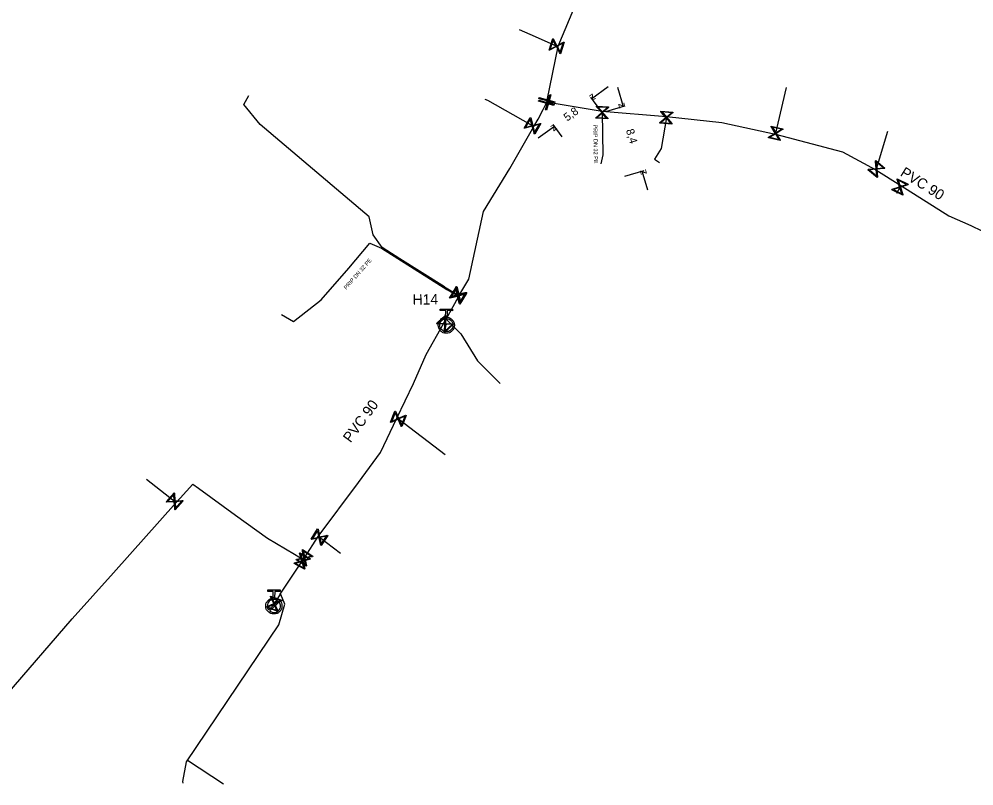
# Model space of a CAD drawing. Extents: x -641905 to -641246, y -1111750 to -1110210.
# Drawn here: x -641545.3 to -641426.1, y -1110592 to -1110496.2 of the extents above; entities that cross this region are included whole.
import ezdxf

# ---------------------------------------------------------------- set-up
doc = ezdxf.new("R2010")
doc.units = 0
for name, color, linetype in [('Default', 7, 'Continuous'), ('VP Hydrant', 7, 'Continuous'), ('VP Hydrant - popis', 7, 'Continuous'), ('VP Kótování', 7, 'Continuous'), ('VP Popis přípojky', 7, 'Continuous'), ('VP Přípojka', 7, 'Continuous'), ('VP Řad', 7, 'Continuous'), ('VP Řad - popis', 7, 'Continuous'), ('VP Šoupě', 7, 'Continuous')]:
    doc.layers.add(name, color=color, linetype=linetype)

msp = doc.modelspace()

# ---------------------------------------------------------------- linework, layer by layer
at = {"layer": 'Default'}
for points in [[(-641491.88, -1110533.45), (-641491.52, -1110533.49), (-641491.27, -1110533.75), (-641490.98, -1110534.04), (-641490.98, -1110534.46), (-641490.98, -1110534.87), (-641491.28, -1110535.16), (-641491.57, -1110535.45), (-641491.99, -1110535.45), (-641492.4, -1110535.45), (-641492.69, -1110535.15), (-641492.98, -1110534.86), (-641492.98, -1110534.45), (-641492.98, -1110534.03), (-641492.69, -1110533.74), (-641492.43, -1110533.48), (-641492.07, -1110533.45)], [(-641491.98, -1110533.64), (-641492.32, -1110533.63), (-641492.55, -1110533.87), (-641492.79, -1110534.11), (-641492.79, -1110534.44), (-641492.8, -1110534.78), (-641492.56, -1110535.02), (-641492.32, -1110535.26), (-641491.99, -1110535.26), (-641491.65, -1110535.26), (-641491.41, -1110535.03), (-641491.17, -1110534.79), (-641491.17, -1110534.45), (-641491.17, -1110534.11), (-641491.4, -1110533.88), (-641491.64, -1110533.64), (-641491.98, -1110533.64)], [(-641513.42, -1110568.51), (-641513.06, -1110568.54), (-641512.8, -1110568.8), (-641512.51, -1110569.1), (-641512.51, -1110569.51), (-641512.52, -1110569.93), (-641512.81, -1110570.22), (-641513.1, -1110570.51), (-641513.52, -1110570.51), (-641513.93, -1110570.5), (-641514.22, -1110570.21), (-641514.52, -1110569.92), (-641514.51, -1110569.5), (-641514.51, -1110569.09), (-641514.22, -1110568.8), (-641513.96, -1110568.54), (-641513.6, -1110568.51)], [(-641513, -1110568.87), (-641513.22, -1110568.69), (-641513.51, -1110568.69), (-641513.85, -1110568.69), (-641514.09, -1110568.93), (-641514.33, -1110569.16), (-641514.33, -1110569.5), (-641514.33, -1110569.79), (-641514.15, -1110570.01)], [(-641514.02, -1110570.14), (-641513.81, -1110570.32), (-641513.52, -1110570.32), (-641513.18, -1110570.32), (-641512.94, -1110570.08), (-641512.7, -1110569.85), (-641512.7, -1110569.51), (-641512.7, -1110569.22), (-641512.87, -1110569)]]:
    msp.add_open_spline(points, degree=3, dxfattribs=at)
at = {"layer": 'VP Hydrant'}
for points in [[(-641492.07, -1110533.45), (-641492.06, -1110532.63), (-641492.75, -1110532.63), (-641492.75, -1110532.45), (-641491.19, -1110532.45), (-641491.19, -1110532.64), (-641491.88, -1110532.63), (-641491.88, -1110533.45)], [(-641513.6, -1110568.51), (-641513.6, -1110567.69), (-641514.28, -1110567.69), (-641514.28, -1110567.5), (-641512.72, -1110567.51), (-641512.72, -1110567.69), (-641513.41, -1110567.69), (-641513.42, -1110568.51)], [(-641514.15, -1110570.01), (-641513, -1110568.87)], [(-641512.87, -1110569), (-641514.02, -1110570.14)]]:
    msp.add_lwpolyline(points, dxfattribs=at)
at = {"layer": 'VP Kótování'}
for points in [[(-641471.79, -1110504.7), (-641473.81, -1110506.18)], [(-641470.61, -1110504.75), (-641469.91, -1110507.15)], [(-641472.83, -1110507.52), (-641473.95, -1110505.97)], [(-641472.05, -1110507.78), (-641469.67, -1110507.08)], [(-641480.51, -1110511.07), (-641478.49, -1110509.59)], [(-641477.51, -1110510.94), (-641478.64, -1110509.39)], [(-641469.68, -1110515.84), (-641467.29, -1110515.14)], [(-641466.83, -1110517.6), (-641467.53, -1110515.21)]]:
    msp.add_lwpolyline(points, dxfattribs=at)
at = {"layer": 'VP Přípojka'}
for points in [[(-641478.05, -1110499.66), (-641478.21, -1110499.61), (-641481.53, -1110498.14), (-641482.83, -1110497.56)], [(-641450.89, -1110510.61), (-641450.84, -1110510.49), (-641449.48, -1110504.79)], [(-641497.77, -1110526.15), (-641500, -1110524.75), (-641501.13, -1110523.18), (-641501.62, -1110520.94), (-641515.25, -1110509.4), (-641517.29, -1110506.9), (-641516.63, -1110505.77)], [(-641481.05, -1110509.66), (-641481.22, -1110509.56), (-641481.42, -1110509.44), (-641486.8, -1110506.39), (-641487.11, -1110506.26)], [(-641472.51, -1110507.72), (-641472.52, -1110507.9), (-641472.42, -1110513.2), (-641472.68, -1110514.32)], [(-641464.49, -1110508.41), (-641464.5, -1110508.53), (-641465.16, -1110512.38), (-641465.98, -1110513.73), (-641465.34, -1110514.13)], [(-641438.36, -1110515.06), (-641438.26, -1110514.94), (-641436.83, -1110510.21)], [(-641435.7, -1110517.96), (-641435.32, -1110517.2)], [(-641435.32, -1110517.2), (-641435.23, -1110517.02)], [(-641512.58, -1110533.12), (-641511.08, -1110534), (-641507.6, -1110531.28), (-641504.14, -1110527.32), (-641501.53, -1110524.21), (-641500.07, -1110524.85), (-641491.9, -1110529.99), (-641490.54, -1110530.8)], [(-641492.19, -1110529.66), (-641497.77, -1110526.15)], [(-641492.19, -1110529.66), (-641490.47, -1110530.7), (-641490.4, -1110530.78)], [(-641490.54, -1110530.8), (-641490.46, -1110530.91)], [(-641491.98, -1110534.45), (-641492.13, -1110534.28), (-641492.29, -1110534.19)], [(-641492.02, -1110533.7), (-641491.95, -1110533.73), (-641490.17, -1110535.55), (-641488.09, -1110538.91), (-641485.24, -1110541.74)], [(-641498.15, -1110546.07), (-641497.97, -1110546.14), (-641492.14, -1110550.62)], [(-641525.73, -1110556.61), (-641525.91, -1110556.45), (-641529.44, -1110553.71)], [(-641507.97, -1110560.85), (-641507.83, -1110560.94), (-641505.19, -1110562.91)], [(-641512.74, -1110568.02), (-641513.48, -1110569.24), (-641513.52, -1110569.5)], [(-641519.79, -1110591.77), (-641524.31, -1110588.81)]]:
    msp.add_lwpolyline(points, dxfattribs=at)
at = {"layer": 'VP Řad'}
for points in [[(-641472.59, -1110486.61), (-641478.05, -1110499.66), (-641479.43, -1110506.37), (-641479.47, -1110506.59)], [(-641509.87, -1110563.7), (-641509.71, -1110563.52), (-641507.97, -1110560.85), (-641502.96, -1110554.08), (-641500.21, -1110550.36), (-641498.15, -1110546.07), (-641496.08, -1110541.72), (-641494.49, -1110538.1), (-641492.29, -1110534.19), (-641492.02, -1110533.7), (-641490.46, -1110530.91), (-641490.4, -1110530.78), (-641489.19, -1110528.69), (-641487.32, -1110520.26), (-641484.05, -1110514.87), (-641481.05, -1110509.66), (-641480.51, -1110508.72), (-641479.89, -1110507.54), (-641479.49, -1110506.7), (-641479.47, -1110506.59)], [(-641479.47, -1110506.59), (-641479.27, -1110506.62), (-641472.51, -1110507.72), (-641464.49, -1110508.41), (-641457.56, -1110509.13), (-641450.89, -1110510.61), (-641442.5, -1110512.82), (-641438.36, -1110515.06), (-641435.23, -1110517.02), (-641429.22, -1110520.79), (-641426.48, -1110522), (-641418.24, -1110525.99), (-641418.01, -1110526.1), (-641417.95, -1110526.12)], [(-641606.72, -1110649.72), (-641606.63, -1110649.64), (-641606.61, -1110649.53), (-641606.49, -1110649.41), (-641597.96, -1110641.06), (-641597.05, -1110639.76), (-641582.85, -1110623.35), (-641570.58, -1110609.06), (-641560.21, -1110596.51), (-641554.97, -1110589.92), (-641538.7, -1110571.11), (-641533.56, -1110565.36), (-641525.73, -1110556.61), (-641525.22, -1110556.04), (-641523.66, -1110554.29), (-641522.92, -1110554.82), (-641518.3, -1110558.16), (-641514.31, -1110561.04), (-641510.94, -1110563.03), (-641509.87, -1110563.7)], [(-641512.74, -1110568.02), (-641509.98, -1110563.9), (-641509.98, -1110563.9), (-641509.87, -1110563.7)], [(-641524.84, -1110591.63), (-641524.89, -1110591.45), (-641524.43, -1110588.98), (-641512.91, -1110571.86), (-641512.13, -1110569.29), (-641512.66, -1110568.07), (-641512.74, -1110568.02)]]:
    msp.add_lwpolyline(points, dxfattribs=at)
at = {"layer": 'VP Šoupě'}
for points in [[(-641477.27, -1110499.12), (-641477.72, -1110500.55), (-641477.78, -1110500.53), (-641477.84, -1110500.41), (-641478.23, -1110499.67), (-641479.09, -1110500.12), (-641479.15, -1110500.1), (-641478.7, -1110498.67), (-641478.64, -1110498.69), (-641478.19, -1110499.55), (-641477.45, -1110499.16), (-641477.33, -1110499.1), (-641477.27, -1110499.12)], [(-641479.01, -1110499.98), (-641478.27, -1110499.59), (-641478.66, -1110498.85), (-641479.01, -1110499.98)], [(-641477.41, -1110499.24), (-641478.15, -1110499.63), (-641477.76, -1110500.37), (-641477.41, -1110499.24)], [(-641478.49, -1110506.7), (-641480.41, -1110506.17), (-641480.38, -1110506.04), (-641478.45, -1110506.58), (-641478.49, -1110506.7)], [(-641479.6, -1110507.57), (-641479.06, -1110505.64), (-641478.94, -1110505.68), (-641479.48, -1110507.6), (-641479.6, -1110507.57)], [(-641478.54, -1110507.03), (-641480.47, -1110506.49), (-641480.44, -1110506.37), (-641478.51, -1110506.91), (-641478.54, -1110507.03)], [(-641473.23, -1110507.11), (-641471.73, -1110507.19), (-641471.73, -1110507.26), (-641471.83, -1110507.34), (-641472.46, -1110507.9), (-641471.81, -1110508.62), (-641471.81, -1110508.69), (-641473.31, -1110508.61), (-641473.31, -1110508.54), (-641472.58, -1110507.9), (-641473.14, -1110507.27), (-641473.23, -1110507.18), (-641473.23, -1110507.11)], [(-641473.08, -1110507.21), (-641472.52, -1110507.84), (-641471.89, -1110507.28), (-641473.08, -1110507.21)], [(-641480.19, -1110509.28), (-641480.94, -1110510.58), (-641481, -1110510.55), (-641481.03, -1110510.42), (-641481.25, -1110509.61), (-641482.19, -1110509.86), (-641482.24, -1110509.83), (-641481.49, -1110508.53), (-641481.43, -1110508.56), (-641481.19, -1110509.5), (-641480.37, -1110509.29), (-641480.25, -1110509.25), (-641480.19, -1110509.28)], [(-641471.96, -1110508.59), (-641472.52, -1110507.96), (-641473.15, -1110508.52), (-641471.96, -1110508.59)], [(-641465.18, -1110507.72), (-641463.69, -1110507.85), (-641463.69, -1110507.92), (-641463.79, -1110507.99), (-641464.44, -1110508.53), (-641463.81, -1110509.28), (-641463.82, -1110509.34), (-641465.31, -1110509.21), (-641465.31, -1110509.14), (-641464.56, -1110508.52), (-641465.1, -1110507.88), (-641465.19, -1110507.78), (-641465.18, -1110507.72)], [(-641463.96, -1110509.24), (-641464.51, -1110508.59), (-641465.15, -1110509.13), (-641463.96, -1110509.24)], [(-641465.03, -1110507.82), (-641464.49, -1110508.47), (-641463.85, -1110507.93), (-641465.03, -1110507.82)], [(-641482.08, -1110509.75), (-641481.27, -1110509.53), (-641481.49, -1110508.71), (-641482.08, -1110509.75)], [(-641480.35, -1110509.37), (-641481.16, -1110509.59), (-641480.95, -1110510.4), (-641480.35, -1110509.37)], [(-641451.4, -1110509.59), (-641449.94, -1110509.93), (-641449.95, -1110510), (-641450.06, -1110510.06), (-641450.78, -1110510.5), (-641450.27, -1110511.33), (-641450.28, -1110511.39), (-641451.74, -1110511.05), (-641451.73, -1110510.98), (-641450.9, -1110510.47), (-641451.34, -1110509.76), (-641451.41, -1110509.65), (-641451.4, -1110509.59)], [(-641451.26, -1110509.71), (-641450.82, -1110510.43), (-641450.11, -1110509.99), (-641451.26, -1110509.71)], [(-641450.41, -1110511.27), (-641450.85, -1110510.55), (-641451.57, -1110510.99), (-641450.41, -1110511.27)], [(-641438.36, -1110513.88), (-641437.2, -1110514.84), (-641437.25, -1110514.9), (-641437.37, -1110514.9), (-641438.21, -1110514.98), (-641438.12, -1110515.95), (-641438.16, -1110516), (-641439.32, -1110515.04), (-641439.27, -1110514.99), (-641438.31, -1110514.9), (-641438.38, -1110514.06), (-641438.4, -1110513.93), (-641438.36, -1110513.88)], [(-641438.3, -1110514.06), (-641438.22, -1110514.89), (-641437.39, -1110514.82), (-641438.3, -1110514.06)], [(-641438.22, -1110515.83), (-641438.3, -1110514.99), (-641439.14, -1110515.06), (-641438.22, -1110515.83)], [(-641435.66, -1110516.19), (-641434.31, -1110516.86), (-641434.34, -1110516.92), (-641434.47, -1110516.96), (-641435.26, -1110517.23), (-641434.95, -1110518.15), (-641434.98, -1110518.21), (-641436.33, -1110517.53), (-641436.3, -1110517.48), (-641435.37, -1110517.17), (-641435.64, -1110516.37), (-641435.68, -1110516.25), (-641435.66, -1110516.19)], [(-641435.56, -1110516.35), (-641435.29, -1110517.14), (-641434.5, -1110516.88), (-641435.56, -1110516.35)], [(-641435.08, -1110518.05), (-641435.35, -1110517.25), (-641436.14, -1110517.52), (-641435.08, -1110518.05)], [(-641489.51, -1110530.54), (-641490.28, -1110531.83), (-641490.34, -1110531.79), (-641490.36, -1110531.67), (-641490.57, -1110530.85), (-641491.51, -1110531.09), (-641491.57, -1110531.06), (-641490.8, -1110529.77), (-641490.74, -1110529.81), (-641490.51, -1110530.75), (-641489.69, -1110530.54), (-641489.57, -1110530.51), (-641489.51, -1110530.54)], [(-641489.42, -1110530.38), (-641490.2, -1110531.67), (-641490.25, -1110531.64), (-641490.28, -1110531.51), (-641490.48, -1110530.69), (-641491.43, -1110530.93), (-641491.48, -1110530.9), (-641490.71, -1110529.61), (-641490.65, -1110529.64), (-641490.42, -1110530.59), (-641489.61, -1110530.38), (-641489.48, -1110530.35), (-641489.42, -1110530.38)], [(-641491.41, -1110530.98), (-641490.59, -1110530.77), (-641490.8, -1110529.95), (-641491.41, -1110530.98)], [(-641491.32, -1110530.81), (-641490.51, -1110530.61), (-641490.71, -1110529.79), (-641491.32, -1110530.81)], [(-641489.67, -1110530.63), (-641490.49, -1110530.83), (-641490.28, -1110531.64), (-641489.67, -1110530.63)], [(-641489.59, -1110530.47), (-641490.4, -1110530.67), (-641490.2, -1110531.49), (-641489.59, -1110530.47)], [(-641493.19, -1110534.25), (-641492.1, -1110533.22), (-641492.05, -1110533.27), (-641492.06, -1110533.4), (-641492.09, -1110534.24), (-641491.11, -1110534.27), (-641491.07, -1110534.31), (-641492.16, -1110535.34), (-641492.21, -1110535.29), (-641492.18, -1110534.32), (-641493.02, -1110534.3), (-641493.15, -1110534.29), (-641493.19, -1110534.25)], [(-641493.01, -1110534.21), (-641492.17, -1110534.23), (-641492.15, -1110533.4), (-641493.01, -1110534.21)], [(-641491.25, -1110534.35), (-641492.09, -1110534.32), (-641492.11, -1110535.16), (-641491.25, -1110534.35)], [(-641497, -1110545.71), (-641497.54, -1110547.11), (-641497.6, -1110547.09), (-641497.65, -1110546.97), (-641497.99, -1110546.2), (-641498.88, -1110546.59), (-641498.94, -1110546.57), (-641498.4, -1110545.17), (-641498.34, -1110545.19), (-641497.95, -1110546.08), (-641497.18, -1110545.74), (-641497.06, -1110545.69), (-641497, -1110545.71)], [(-641498.8, -1110546.46), (-641498.03, -1110546.12), (-641498.37, -1110545.35), (-641498.8, -1110546.46)], [(-641497.14, -1110545.83), (-641497.91, -1110546.16), (-641497.57, -1110546.93), (-641497.14, -1110545.83)], [(-641524.85, -1110556.39), (-641525.85, -1110557.51), (-641525.9, -1110557.46), (-641525.9, -1110557.34), (-641525.95, -1110556.5), (-641526.92, -1110556.55), (-641526.97, -1110556.51), (-641525.97, -1110555.39), (-641525.92, -1110555.43), (-641525.87, -1110556.4), (-641525.03, -1110556.36), (-641524.9, -1110556.35), (-641524.85, -1110556.39)], [(-641526.8, -1110556.46), (-641525.96, -1110556.41), (-641526, -1110555.57), (-641526.8, -1110556.46)], [(-641525.03, -1110556.44), (-641525.86, -1110556.49), (-641525.81, -1110557.33), (-641525.03, -1110556.44)], [(-641506.79, -1110560.72), (-641507.6, -1110561.98), (-641507.66, -1110561.94), (-641507.68, -1110561.81), (-641507.86, -1110560.99), (-641508.81, -1110561.2), (-641508.87, -1110561.17), (-641508.06, -1110559.9), (-641508, -1110559.94), (-641507.8, -1110560.89), (-641506.97, -1110560.71), (-641506.85, -1110560.68), (-641506.79, -1110560.72)], [(-641508.71, -1110561.09), (-641507.88, -1110560.91), (-641508.06, -1110560.09), (-641508.71, -1110561.09)], [(-641506.96, -1110560.8), (-641507.78, -1110560.98), (-641507.6, -1110561.79), (-641506.96, -1110560.8)], [(-641510.27, -1110562.88), (-641508.96, -1110563.61), (-641508.99, -1110563.66), (-641509.11, -1110563.7), (-641509.92, -1110563.93), (-641509.65, -1110564.86), (-641509.68, -1110564.92), (-641510.99, -1110564.2), (-641510.96, -1110564.14), (-641510.03, -1110563.87), (-641510.26, -1110563.06), (-641510.3, -1110562.94), (-641510.27, -1110562.88)], [(-641509.93, -1110562.48), (-641508.67, -1110563.3), (-641508.71, -1110563.36), (-641508.83, -1110563.38), (-641509.66, -1110563.55), (-641509.45, -1110564.5), (-641509.49, -1110564.56), (-641510.75, -1110563.74), (-641510.71, -1110563.68), (-641509.76, -1110563.49), (-641509.93, -1110562.66), (-641509.96, -1110562.54), (-641509.93, -1110562.48)], [(-641510.18, -1110563.04), (-641509.94, -1110563.85), (-641509.14, -1110563.61), (-641510.18, -1110563.04)], [(-641509.85, -1110562.65), (-641509.67, -1110563.47), (-641508.86, -1110563.29), (-641509.85, -1110562.65)], [(-641509.77, -1110564.76), (-641510, -1110563.96), (-641510.81, -1110564.19), (-641509.77, -1110564.76)], [(-641509.57, -1110564.4), (-641509.74, -1110563.57), (-641510.57, -1110563.75), (-641509.57, -1110564.4)], [(-641513.92, -1110568.28), (-641512.52, -1110568.8), (-641512.54, -1110568.86), (-641512.66, -1110568.91), (-641513.42, -1110569.26), (-641513.01, -1110570.14), (-641513.04, -1110570.2), (-641514.44, -1110569.68), (-641514.42, -1110569.62), (-641513.54, -1110569.22), (-641513.89, -1110568.45), (-641513.95, -1110568.34), (-641513.92, -1110568.28)], [(-641513.15, -1110570.06), (-641513.5, -1110569.3), (-641514.26, -1110569.65), (-641513.15, -1110570.06)], [(-641513.81, -1110568.42), (-641513.46, -1110569.18), (-641512.7, -1110568.83), (-641513.81, -1110568.42)]]:
    msp.add_lwpolyline(points, dxfattribs=at)

# ---------------------------------------------------------------- texts
at = {"layer": 'VP Hydrant - popis'}
msp.add_text('H14', height=1.3, rotation=1, dxfattribs=at).set_placement((-641496.18, -1110531.91))
at = {"layer": 'VP Kótování'}
for s, rotation, p in [('z', 216.1031, (-641473.7, -1110505.48)), ('5,8', 36.1031, (-641476.88, -1110509.04)), ('z', 286.4155, (-641470.53, -1110506.81)), ('z', 36.1031, (-641478.6, -1110510.29)), ('8,4', 286.4155, (-641469.56, -1110510.1)), ('z', 106.4155, (-641466.91, -1110515.54))]:
    msp.add_text(s, height=1, rotation=rotation, dxfattribs=at).set_placement(p)
at = {"layer": 'VP Popis přípojky'}
for rotation, p in [(271.0809, (-641473.63, -1110509.4)), (48.8407, (-641504.47, -1110530.05))]:
    msp.add_text('PRIP DN 32 PE', height=0.5, rotation=rotation, dxfattribs=at).set_placement(p)
at = {"layer": 'VP Řad - popis'}
for rotation, p in [(327.9004, (-641435.39, -1110515.72)), (53.5077, (-641503.95, -1110549.21))]:
    msp.add_text('PVC 90', height=1.3, rotation=rotation, dxfattribs=at).set_placement(p)

doc.saveas('drawing.dxf')
